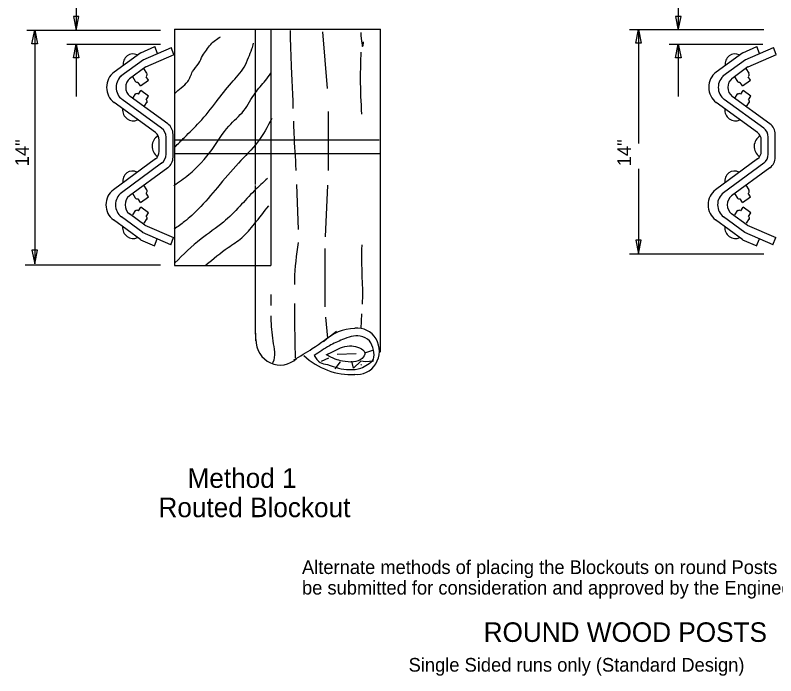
# Model space of a CAD drawing. Extents: x -0.7 to 88.8, y -25.9 to 22.
# Drawn here: x 62.32 to 70.1, y -25.88 to -19.12 of the extents above; entities that cross this region are included whole.
import ezdxf

# ---------------------------------------------------------------- set-up
doc = ezdxf.new("R2010")
doc.units = 0
doc.layers.add('Default', color=7, linetype='Continuous')

msp = doc.modelspace()

# ---------------------------------------------------------------- linework, layer by layer
at = {"layer": 'Default'}
for p, q in [((62.944480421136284, -18.622847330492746), (62.944480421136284, -19.27642783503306)), ((69.1012304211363, -18.622847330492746), (69.1012304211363, -19.27642783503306)), ((62.43998042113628, -19.27642783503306), (63.80756375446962, -19.27642783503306)), ((62.520147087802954, -19.27642783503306), (62.520147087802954, -20.902761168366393)), ((63.94881375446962, -19.26442783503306), (66.05548042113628, -19.26442783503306)), ((63.94881375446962, -19.26442783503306), (63.94881375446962, -21.681261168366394)), ((64.77906375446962, -20.85459450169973), (64.77906375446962, -19.26442783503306)), ((64.93356375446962, -19.26442783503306), (64.93356375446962, -21.681261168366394)), ((66.05548042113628, -22.567594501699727), (66.05548042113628, -19.26442783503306)), ((68.60064708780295, -19.269094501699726), (69.97489708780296, -19.269094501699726)), ((68.69514708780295, -19.269094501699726), (68.69514708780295, -20.435761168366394)), ((65.46448042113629, -19.29342783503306), (65.51223042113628, -19.87292783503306)), ((62.85006375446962, -19.419261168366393), (63.80756375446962, -19.419261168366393)), ((62.944480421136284, -19.419261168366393), (62.944480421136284, -19.954761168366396)), ((69.00681375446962, -19.419261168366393), (69.96431375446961, -19.419261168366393)), ((69.1012304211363, -19.419261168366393), (69.1012304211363, -19.954761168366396)), ((63.604230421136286, -19.50642783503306), (63.33131375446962, -19.706261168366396)), ((63.603980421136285, -19.50592783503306), (63.747897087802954, -19.443261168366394)), ((63.62873042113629, -19.57892783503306), (63.91814708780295, -19.45259450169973)), ((63.77539708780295, -19.513261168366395), (63.74831375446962, -19.44392783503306)), ((63.94431375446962, -19.522927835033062), (63.91731375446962, -19.453594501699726)), ((69.76098042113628, -19.50642783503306), (69.48806375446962, -19.706261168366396)), ((69.76073042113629, -19.50592783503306), (69.90464708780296, -19.443261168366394)), ((69.78548042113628, -19.57892783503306), (70.07489708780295, -19.45259450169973)), ((69.93214708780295, -19.513261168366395), (69.90506375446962, -19.44392783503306)), ((70.10106375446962, -19.522927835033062), (70.07406375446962, -19.453594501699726)), ((63.63123042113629, -19.57759450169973), (63.40123042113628, -19.746094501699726)), ((63.65789708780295, -19.649594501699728), (63.947397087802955, -19.523261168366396)), ((69.78798042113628, -19.57759450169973), (69.55798042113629, -19.746094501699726)), ((69.81464708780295, -19.649594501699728), (70.10414708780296, -19.523261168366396)), ((63.65706375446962, -19.64992783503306), (63.49031375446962, -19.772094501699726)), ((63.667730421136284, -19.716761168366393), (63.63756375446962, -19.669427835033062)), ((69.81381375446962, -19.64992783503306), (69.64706375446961, -19.772094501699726)), ((69.82448042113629, -19.716761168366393), (69.79431375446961, -19.669427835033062)), ((63.68289708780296, -19.786761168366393), (63.66023042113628, -19.751261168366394)), ((69.83964708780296, -19.786761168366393), (69.8169804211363, -19.751261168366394)), ((63.551897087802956, -19.799261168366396), (63.52281375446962, -19.753594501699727)), ((63.600647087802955, -19.845761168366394), (63.577480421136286, -19.809427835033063)), ((63.60048042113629, -19.845261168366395), (63.682980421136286, -19.786761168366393)), ((69.70864708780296, -19.799261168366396), (69.67956375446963, -19.753594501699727)), ((69.75739708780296, -19.845761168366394), (69.73423042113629, -19.809427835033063)), ((69.75723042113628, -19.845261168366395), (69.83973042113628, -19.786761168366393)), ((63.58223042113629, -19.931594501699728), (63.606897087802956, -19.89292783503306)), ((63.685397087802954, -19.95059450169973), (63.606730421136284, -19.89309450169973)), ((69.73898042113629, -19.931594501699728), (69.76364708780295, -19.89292783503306)), ((69.84214708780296, -19.95059450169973), (69.7634804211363, -19.89309450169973)), ((63.81806375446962, -20.278261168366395), (63.41414708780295, -19.98392783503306)), ((63.88123042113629, -20.233261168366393), (63.49656375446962, -19.952927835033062)), ((63.522230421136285, -19.97192783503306), (63.55398042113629, -19.92192783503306)), ((63.66114708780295, -19.98909450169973), (63.68506375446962, -19.951427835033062)), ((69.97481375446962, -20.278261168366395), (69.57089708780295, -19.98392783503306)), ((70.03798042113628, -20.233261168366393), (69.65331375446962, -19.952927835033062)), ((69.67898042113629, -19.97192783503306), (69.71073042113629, -19.92192783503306)), ((69.81789708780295, -19.98909450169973), (69.84181375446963, -19.951427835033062)), ((63.75489708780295, -20.323261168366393), (63.331647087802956, -20.01492783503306)), ((63.64031375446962, -20.057927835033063), (63.67131375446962, -20.009427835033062)), ((69.91164708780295, -20.323261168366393), (69.48839708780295, -20.01492783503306)), ((69.79706375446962, -20.057927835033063), (69.82806375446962, -20.009427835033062)), ((65.51964708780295, -20.10642783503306), (65.51964708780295, -20.71092783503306)), ((63.86406375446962, -20.544261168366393), (63.86406375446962, -20.37092783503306)), ((63.93489708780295, -20.573761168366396), (63.93489708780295, -20.341261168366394)), ((70.02081375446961, -20.544261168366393), (70.02081375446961, -20.37092783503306)), ((70.09164708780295, -20.573761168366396), (70.09164708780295, -20.341261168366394)), ((63.793230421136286, -20.514761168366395), (63.793230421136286, -20.40042783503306)), ((63.86406375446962, -20.46292783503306), (63.86406375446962, -20.452094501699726)), ((63.947647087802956, -20.396427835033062), (66.04356375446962, -20.396427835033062)), ((69.94998042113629, -20.514761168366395), (69.94998042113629, -20.40042783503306)), ((70.02081375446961, -20.46292783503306), (70.02081375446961, -20.452094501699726)), ((63.75506375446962, -20.59192783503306), (63.32473042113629, -20.90742783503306)), ((63.95231375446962, -20.537261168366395), (66.04806375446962, -20.537261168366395)), ((69.91181375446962, -20.59192783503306), (69.48148042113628, -20.90742783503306)), ((63.818230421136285, -20.636761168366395), (63.407147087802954, -20.938094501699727)), ((63.88148042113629, -20.681761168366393), (63.48981375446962, -20.96892783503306)), ((69.97498042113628, -20.636761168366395), (69.56389708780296, -20.938094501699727)), ((70.03823042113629, -20.681761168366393), (69.64656375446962, -20.96892783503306)), ((68.69514708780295, -20.69392783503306), (68.69514708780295, -21.56359450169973)), ((62.520147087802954, -20.902761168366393), (62.520147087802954, -21.666094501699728)), ((63.667730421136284, -20.90942783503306), (63.63756375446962, -20.862094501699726)), ((64.77906375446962, -21.681261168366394), (64.77906375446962, -20.864594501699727)), ((65.19614708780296, -20.85309450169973), (65.21348042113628, -21.315594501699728)), ((65.51473042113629, -20.860761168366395), (65.49089708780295, -21.387427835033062)), ((69.82448042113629, -20.90942783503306), (69.79431375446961, -20.862094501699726)), ((63.551897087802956, -20.99209450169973), (63.52281375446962, -20.94642783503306)), ((63.60048042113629, -21.038094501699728), (63.682980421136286, -20.97942783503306)), ((63.68289708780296, -20.97959450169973), (63.66023042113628, -20.944094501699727)), ((69.70864708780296, -20.99209450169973), (69.67956375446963, -20.94642783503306)), ((69.75723042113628, -21.038094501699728), (69.83973042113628, -20.97942783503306)), ((69.83964708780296, -20.97959450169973), (69.8169804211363, -20.944094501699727)), ((63.600647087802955, -21.038427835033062), (63.577480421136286, -21.002094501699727)), ((69.75739708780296, -21.038427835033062), (69.73423042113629, -21.002094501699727)), ((63.522230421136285, -21.164594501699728), (63.55398042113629, -21.114594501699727)), ((63.58223042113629, -21.124261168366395), (63.606897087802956, -21.085594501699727)), ((63.685397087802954, -21.143261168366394), (63.606730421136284, -21.085761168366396)), ((63.66114708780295, -21.181761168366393), (63.68506375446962, -21.144261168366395)), ((69.67898042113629, -21.164594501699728), (69.71073042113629, -21.114594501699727)), ((69.73898042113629, -21.124261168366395), (69.76364708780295, -21.085594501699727)), ((69.84214708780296, -21.143261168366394), (69.7634804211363, -21.085761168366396)), ((69.81789708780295, -21.181761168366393), (69.84181375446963, -21.144261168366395)), ((63.60448042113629, -21.419761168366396), (63.32506375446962, -21.21592783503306)), ((63.62531375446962, -21.343761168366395), (63.407480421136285, -21.185094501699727)), ((63.64739708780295, -21.268761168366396), (63.48998042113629, -21.154094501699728)), ((63.64031375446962, -21.250761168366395), (63.67131375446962, -21.202094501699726)), ((69.76123042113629, -21.419761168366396), (69.48181375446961, -21.21592783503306)), ((69.78206375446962, -21.343761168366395), (69.56423042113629, -21.185094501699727)), ((69.80414708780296, -21.268761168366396), (69.64673042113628, -21.154094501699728)), ((69.79706375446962, -21.250761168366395), (69.82806375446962, -21.202094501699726)), ((63.64739708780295, -21.268261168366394), (63.94106375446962, -21.396427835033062)), ((69.80414708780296, -21.268261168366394), (70.09781375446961, -21.396427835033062)), ((63.913147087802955, -21.469427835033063), (63.62373042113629, -21.343261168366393)), ((70.06989708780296, -21.469427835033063), (69.78048042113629, -21.343261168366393)), ((63.602230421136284, -21.418761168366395), (63.74614708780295, -21.48159450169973)), ((63.74531375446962, -21.481261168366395), (63.773647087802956, -21.408761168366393)), ((63.91231375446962, -21.469427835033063), (63.94098042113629, -21.39592783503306)), ((69.75898042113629, -21.418761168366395), (69.90289708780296, -21.48159450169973)), ((69.90206375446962, -21.481261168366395), (69.93039708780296, -21.408761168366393)), ((70.06906375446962, -21.469427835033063), (70.09773042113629, -21.39592783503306)), ((65.48606375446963, -21.507761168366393), (65.48606375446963, -22.105261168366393)), ((68.60064708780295, -21.56359450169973), (69.69931375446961, -21.56359450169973)), ((69.69931375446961, -21.56359450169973), (69.97489708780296, -21.56359450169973)), ((62.423897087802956, -21.67509450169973), (63.80756375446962, -21.67509450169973)), ((63.94881375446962, -21.681261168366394), (64.93356375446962, -21.681261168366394)), ((64.77906375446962, -22.38359450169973), (64.77906375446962, -21.681261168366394)), ((64.93506375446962, -21.977261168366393), (64.93506375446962, -22.09109450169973)), ((65.49323042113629, -22.211261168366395), (65.51298042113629, -22.425261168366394)), ((65.86314708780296, -22.176761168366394), (65.85556375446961, -22.325761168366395)), ((64.78056375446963, -22.453761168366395), (64.78056375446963, -22.375594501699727)), ((65.89589708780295, -22.574761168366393), (65.97656375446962, -22.546261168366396)), ((65.45239708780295, -22.660094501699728), (65.52639708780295, -22.62459450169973)), ((65.61373042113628, -22.58892783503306), (65.80856375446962, -22.58192783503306)), ((65.59348042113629, -22.73842783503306), (65.64731375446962, -22.667261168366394)), ((65.78164708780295, -22.731261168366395), (65.76156375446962, -22.660094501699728)), ((65.85556375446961, -22.660094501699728), (65.78164708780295, -22.731261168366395)), ((65.90264708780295, -22.667261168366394), (65.85556375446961, -22.660094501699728)), ((65.86231375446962, -22.702761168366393), (65.85556375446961, -22.695761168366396)), ((65.98331375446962, -22.660094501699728), (65.90264708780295, -22.667261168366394))]:
    msp.add_line(p, q, dxfattribs=at)
for points in [[(62.916480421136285, -19.13642783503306), (62.944480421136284, -19.27642783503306), (62.97248042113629, -19.13642783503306)], [(69.07323042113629, -19.13642783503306), (69.1012304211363, -19.27642783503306), (69.12923042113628, -19.13642783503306)], [(62.492147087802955, -19.416427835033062), (62.520147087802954, -19.27642783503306), (62.54814708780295, -19.416427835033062)], [(68.66714708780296, -19.409094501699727), (68.69514708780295, -19.269094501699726), (68.72314708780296, -19.409094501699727)], [(62.916480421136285, -19.559261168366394), (62.944480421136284, -19.419261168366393), (62.97248042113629, -19.559261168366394)], [(69.07323042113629, -19.559261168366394), (69.1012304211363, -19.419261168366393), (69.12923042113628, -19.559261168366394)], [(68.66714708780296, -21.42359450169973), (68.69514708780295, -21.56359450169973), (68.72314708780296, -21.42359450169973)], [(62.492147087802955, -21.526094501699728), (62.520147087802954, -21.666094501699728), (62.54814708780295, -21.526094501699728)]]:
    msp.add_lwpolyline(points, close=True, dxfattribs=at)
for centre, major_axis, ratio, start_param, end_param in [((63.52391400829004, -19.625280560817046), (-1.7132284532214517e-17, -0.10653593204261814), 0.9445438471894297, 2.6872111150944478, 4.851440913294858), ((69.68066400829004, -19.625280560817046), (-1.7132284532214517e-17, -0.10653593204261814), 0.9445438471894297, 2.6872111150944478, 4.851440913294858), ((63.43209676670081, -19.860464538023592), (-3.014770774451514e-17, -0.18747144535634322), 0.9445438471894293, 3.7470844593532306, 5.680264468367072), ((63.49444191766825, -19.8603564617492), (-2.4118166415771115e-17, -0.14997715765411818), 0.9445438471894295, 3.7471373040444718, 5.680323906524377), ((63.6518216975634, -19.729185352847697), (5.618624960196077e-18, 0.019834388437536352), 0.9445438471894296, 3.7043701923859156, 5.352473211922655), ((69.58884676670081, -19.860464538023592), (-3.014770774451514e-17, -0.18747144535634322), 0.9445438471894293, 3.7470844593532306, 5.680264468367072), ((69.65119191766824, -19.8603564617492), (-2.4118166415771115e-17, -0.14997715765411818), 0.9445438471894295, 3.7471373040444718, 5.680323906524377), ((69.8085716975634, -19.729185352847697), (5.618624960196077e-18, 0.019834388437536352), 0.9445438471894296, 3.7043701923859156, 5.352473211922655), ((63.55680814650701, -19.86026571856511), (-1.8088624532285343e-17, -0.11248286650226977), 0.9445438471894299, 3.747102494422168, 5.680297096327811), ((63.5647711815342, -19.78866168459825), (-3.142739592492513e-18, -0.01954290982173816), 0.9445438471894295, 5.247458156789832, 6.879591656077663), ((69.71355814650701, -19.86026571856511), (-1.8088624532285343e-17, -0.11248286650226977), 0.9445438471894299, 3.747102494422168, 5.680297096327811), ((69.7215211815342, -19.78866168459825), (-3.142739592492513e-18, -0.01954290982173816), 0.9445438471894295, 5.247458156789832, 6.879591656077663), ((63.56645532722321, -19.945122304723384), (5.958650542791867e-18, 0.021034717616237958), 0.9445438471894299, 5.4523006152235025, 7.118325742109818), ((69.72320532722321, -19.945122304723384), (5.958650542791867e-18, 0.021034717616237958), 0.9445438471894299, 5.4523006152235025, 7.118325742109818), ((63.652112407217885, -20.007612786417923), (5.958650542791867e-18, 0.021034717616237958), 0.9445438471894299, 4.196406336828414, 5.735380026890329), ((69.80886240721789, -20.007612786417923), (5.958650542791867e-18, 0.021034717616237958), 0.9445438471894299, 4.196406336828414, 5.735380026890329), ((63.527105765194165, -20.087800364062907), (-1.8497404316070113e-17, -0.11502483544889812), 0.9445438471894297, 4.64065114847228, 6.714316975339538), ((69.68385576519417, -20.087800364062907), (-1.8497404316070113e-17, -0.11502483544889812), 0.9445438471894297, 4.64065114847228, 6.714316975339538), ((63.75779329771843, -20.370894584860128), (3.186380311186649e-17, 0.11248286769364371), 0.9445438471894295, 4.71238898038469, 5.680339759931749), ((63.81091579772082, -20.341332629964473), (3.7174443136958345e-17, 0.13123003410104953), 0.9445438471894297, 4.71238898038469, 5.680267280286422), ((69.91454329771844, -20.370894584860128), (3.186380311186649e-17, 0.11248286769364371), 0.9445438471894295, 4.71238898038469, 5.680339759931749), ((69.96766579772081, -20.341332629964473), (3.7174443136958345e-17, 0.13123003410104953), 0.9445438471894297, 4.71238898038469, 5.680267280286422), ((63.833517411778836, -20.463902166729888), (-1.929587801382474e-17, -0.11999008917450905), 0.9445438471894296, 3.613765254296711, 5.741419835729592), ((63.70467079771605, -20.400475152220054), (2.6553169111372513e-17, 0.09373572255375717), 0.9445438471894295, 4.71238898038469, 5.68037747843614), ((69.99026741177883, -20.463902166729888), (-1.929587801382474e-17, -0.11999008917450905), 0.9445438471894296, 3.613765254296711, 5.741419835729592), ((69.86142079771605, -20.400475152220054), (2.6553169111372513e-17, 0.09373572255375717), 0.9445438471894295, 4.71238898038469, 5.68037747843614), ((63.70467079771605, -20.51483091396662), (-1.5073853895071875e-17, -0.09373572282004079), 0.9445438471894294, 0.6055627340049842, 1.5707963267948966), ((69.86142079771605, -20.51483091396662), (-1.5073853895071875e-17, -0.09373572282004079), 0.9445438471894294, 0.6055627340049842, 1.5707963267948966), ((63.75779329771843, -20.544261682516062), (-1.8088624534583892e-17, -0.11248286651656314), 0.9445438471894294, 0.6056505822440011, 1.5707963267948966), ((63.81091579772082, -20.57384182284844), (-2.110339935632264e-17, -0.13123003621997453), 0.9445438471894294, 0.6055663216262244, 1.5707963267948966), ((69.91454329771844, -20.544261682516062), (-1.8088624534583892e-17, -0.11248286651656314), 0.9445438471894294, 0.6056505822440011, 1.5707963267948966), ((69.96766579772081, -20.57384182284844), (-2.110339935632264e-17, -0.13123003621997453), 0.9445438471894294, 0.6055663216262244, 1.5707963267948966), ((63.520891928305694, -20.82219825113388), (-1.7132284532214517e-17, -0.10653593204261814), 0.9445438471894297, 2.6872111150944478, 4.851440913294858), ((69.67764192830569, -20.82219825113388), (-1.7132284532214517e-17, -0.10653593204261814), 0.9445438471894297, 2.6872111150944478, 4.851440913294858), ((63.425471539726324, -21.061543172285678), (-3.0147707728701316e-17, -0.18747144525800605), 0.9445438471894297, 3.7470910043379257, 5.6802800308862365), ((63.6518216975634, -20.921903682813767), (5.618624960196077e-18, 0.019834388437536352), 0.9445438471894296, 3.7043701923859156, 5.352473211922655), ((69.58222153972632, -21.061543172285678), (-3.0147707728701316e-17, -0.18747144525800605), 0.9445438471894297, 3.7470910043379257, 5.6802800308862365), ((69.8085716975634, -20.921903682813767), (5.618624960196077e-18, 0.019834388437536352), 0.9445438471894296, 3.7043701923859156, 5.352473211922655), ((63.487794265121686, -21.061429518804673), (-2.4118166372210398e-17, -0.14997715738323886), 0.9445438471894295, 3.7471148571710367, 5.680354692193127), ((63.550206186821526, -21.0613220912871), (-1.8088624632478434e-17, -0.11248286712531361), 0.9445438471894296, 3.747102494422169, 5.680258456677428), ((63.5647711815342, -20.981380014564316), (-3.142739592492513e-18, -0.01954290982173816), 0.9445438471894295, 5.247458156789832, 6.879591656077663), ((69.64454426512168, -21.061429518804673), (-2.4118166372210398e-17, -0.14997715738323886), 0.9445438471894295, 3.7471148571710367, 5.680354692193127), ((69.70695618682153, -21.0613220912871), (-1.8088624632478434e-17, -0.11248286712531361), 0.9445438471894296, 3.747102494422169, 5.680258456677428), ((69.7215211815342, -20.981380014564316), (-3.142739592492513e-18, -0.01954290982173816), 0.9445438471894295, 5.247458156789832, 6.879591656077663), ((63.56645532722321, -21.137840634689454), (5.958650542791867e-18, 0.021034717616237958), 0.9445438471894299, 5.4523006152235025, 7.118325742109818), ((69.72320532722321, -21.137840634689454), (5.958650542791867e-18, 0.021034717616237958), 0.9445438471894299, 5.4523006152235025, 7.118325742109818), ((63.652112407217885, -21.20033111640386), (5.958650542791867e-18, 0.021034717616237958), 0.9445438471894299, 4.196406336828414, 5.735380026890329), ((69.80886240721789, -21.20033111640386), (5.958650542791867e-18, 0.021034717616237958), 0.9445438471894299, 4.196406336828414, 5.735380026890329), ((63.527105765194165, -21.291117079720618), (-1.8497404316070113e-17, -0.11502483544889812), 0.9445438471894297, 4.64065114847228, 6.714316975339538), ((69.68385576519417, -21.291117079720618), (-1.8497404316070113e-17, -0.11502483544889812), 0.9445438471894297, 4.64065114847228, 6.714316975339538), ((65.82091726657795, -22.558636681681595), (6.704483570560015e-17, 0.23667593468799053), 0.9445438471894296, 2.997306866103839, 6.4059503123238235), ((65.79860443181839, -22.83380333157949), (1.4392587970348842e-16, 0.5080748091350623), 0.9445438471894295, 0.007203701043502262, 0.7467341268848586), ((65.02991075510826, -22.435876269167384), (-4.245406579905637e-17, -0.2639976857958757), 0.9445438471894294, 4.7265868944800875, 7.018322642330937), ((65.75632652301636, -22.01634665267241), (-1.254338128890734e-16, -0.7800015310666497), 0.9445438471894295, 5.5640474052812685, 6.33577377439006)]:
    msp.add_ellipse(centre, major_axis=major_axis, ratio=ratio, start_param=start_param, end_param=end_param, dxfattribs=at)
for points in [[(65.13148042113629, -19.27942783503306), (65.14339708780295, -19.66542783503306), (65.15681375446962, -19.949927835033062), (65.16123042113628, -20.07742783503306)], [(63.950147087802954, -19.925427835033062), (64.01923042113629, -19.86392783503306), (64.08456375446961, -19.802261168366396), (64.1354804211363, -19.698594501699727), (64.19723042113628, -19.61392783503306), (64.23714708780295, -19.53692783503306), (64.27714708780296, -19.479261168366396), (64.32073042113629, -19.421594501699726), (64.41981375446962, -19.342761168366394)], [(65.85389708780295, -19.300761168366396), (65.87573042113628, -19.437761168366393), (65.8824804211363, -19.394927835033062)], [(63.953730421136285, -20.471594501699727), (64.05189708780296, -20.37159450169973), (64.20448042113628, -20.217761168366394), (64.37881375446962, -20.006261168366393), (64.53148042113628, -19.813927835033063), (64.66214708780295, -19.652427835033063), (64.70581375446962, -19.55609450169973), (64.74214708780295, -19.467761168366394), (64.75823042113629, -19.409927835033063)], [(65.85556375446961, -19.501594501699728), (65.84889708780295, -19.772094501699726), (65.86131375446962, -20.134761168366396)], [(63.942897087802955, -20.86392783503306), (64.09548042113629, -20.75242783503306), (64.33523042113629, -20.494594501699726), (64.50598042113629, -20.256094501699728), (64.65856375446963, -20.09842783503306), (64.77481375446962, -19.917761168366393), (64.88023042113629, -19.790761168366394), (64.93573042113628, -19.716594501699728)], [(64.94639708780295, -20.17942783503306), (64.79864708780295, -20.421261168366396), (64.60381375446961, -20.634761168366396), (64.38873042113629, -20.88359450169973), (64.19389708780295, -21.104094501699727), (64.05281375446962, -21.232261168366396), (63.94523042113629, -21.31042783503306)], [(65.16573042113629, -20.20542783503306), (65.17023042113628, -20.333927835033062), (65.19048042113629, -20.70392783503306), (65.19073042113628, -20.710761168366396)], [(64.89939708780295, -20.791094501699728), (64.76498042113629, -20.919261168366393), (64.61723042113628, -21.075761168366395), (64.44923042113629, -21.239261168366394), (64.22073042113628, -21.410094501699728), (63.95439708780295, -21.655761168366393)], [(64.27164708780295, -21.674761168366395), (64.49864708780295, -21.498427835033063), (64.63673042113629, -21.39842783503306), (64.76756375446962, -21.256261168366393), (64.91356375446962, -21.071594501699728)], [(65.21431375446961, -21.445594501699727), (65.17698042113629, -21.827761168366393), (65.17698042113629, -21.87759450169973)], [(65.86464708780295, -21.47192783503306), (65.86231375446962, -21.529094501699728), (65.86898042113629, -22.062594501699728), (65.86823042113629, -22.077094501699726)], [(65.17698042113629, -22.069761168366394), (65.17698042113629, -22.24042783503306), (65.18364708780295, -22.62459450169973)], [(64.93506375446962, -22.197761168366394), (64.93506375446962, -22.21909450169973), (64.95523042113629, -22.453761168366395), (64.95523042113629, -22.67442783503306), (64.94848042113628, -22.68859450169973)], [(65.17023042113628, -22.64592783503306), (65.35839708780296, -22.532094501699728), (65.60706375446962, -22.354261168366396)], [(65.37856375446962, -22.603261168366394), (65.53306375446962, -22.503594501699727), (65.66748042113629, -22.439594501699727), (65.84889708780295, -22.404094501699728), (65.94298042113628, -22.453761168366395), (65.98331375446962, -22.546261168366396), (65.98331375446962, -22.638761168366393), (65.92281375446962, -22.695761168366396), (65.85556375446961, -22.731261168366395), (65.73464708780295, -22.745427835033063), (65.62714708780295, -22.731261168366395), (65.51298042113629, -22.695761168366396), (65.43898042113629, -22.67442783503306), (65.37856375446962, -22.603261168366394)], [(65.49948042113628, -22.596094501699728), (65.58681375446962, -22.553427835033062), (65.66748042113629, -22.517761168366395), (65.76156375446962, -22.503594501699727), (65.84214708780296, -22.52492783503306), (65.89589708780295, -22.574761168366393), (65.86898042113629, -22.631761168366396), (65.78164708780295, -22.667261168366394), (65.66748042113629, -22.660094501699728), (65.59348042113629, -22.638761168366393), (65.50614708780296, -22.596094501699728)]]:
    msp.add_spline(points, degree=3, dxfattribs=at)

# ---------------------------------------------------------------- texts
for p in [(62.460993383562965, -20.66700914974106), (68.61774338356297, -20.66700914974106)]:
    msp.add_text('14" ', height=0.13999999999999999, rotation=89.99999999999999, dxfattribs=at).set_placement(p)
for s, height, p in [('    Method 1', 0.19999999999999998, (63.78573320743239, -23.95551496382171)), ('Routed Blockout', 0.19999999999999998, (63.78573320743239, -24.25551496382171)), ('Alternate methods of placing the Blockouts on round Posts may', 0.13999999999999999, (65.25332660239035, -24.83660387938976)), ('be submitted for consideration and approved by the Engineer.', 0.13999999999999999, (65.25332660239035, -25.04660387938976)), ('ROUND WOOD POSTS', 0.19999999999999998, (67.11071815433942, -25.530905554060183)), ('Single Sided runs only (Standard Design)', 0.13999999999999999, (66.34348560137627, -25.835104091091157))]:
    msp.add_text(s, height=height, dxfattribs=at).set_placement(p)

doc.saveas('drawing.dxf')
